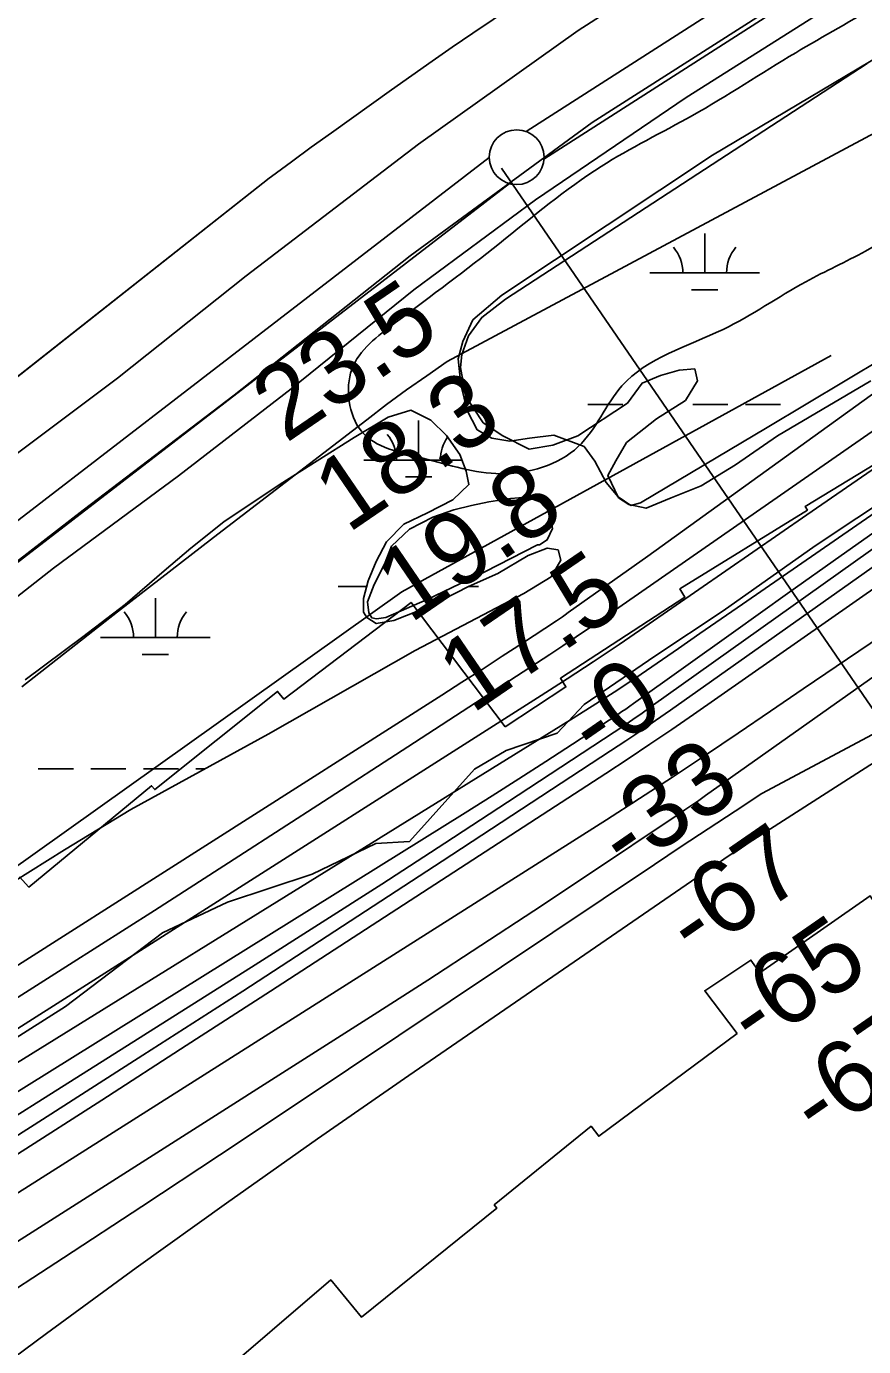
# Model space of a CAD drawing. Extents: x 3477039 to 3515015, y 546746 to 572297.
# Drawn here: x 3486854 to 3487619, y 561977 to 563182 of the extents above; entities that cross this region are included whole.
import ezdxf

# ---------------------------------------------------------------- set-up
doc = ezdxf.new("R2010")
doc.units = 0
for name, color, linetype in [('V-FLOD-BASE', 7, 'Continuous'), ('V-LEVE-TOET', 7, 'Continuous'), ('V-RIVR-EDGE', 7, 'Continuous'), ('V-RIVR-RANG', 7, 'Continuous'), ('V-ROAD-CNTR', 7, 'Continuous'), ('V-RRAP-FSHR', 7, 'Continuous'), ('V-RRAP-RVMT', 7, 'Continuous'), ('V-SITE-VEGE', 7, 'Continuous'), ('V-SURV-LINE', 7, 'Continuous'), ('V-TOPO-DPTH', 7, 'Continuous'), ('V-TOPO-MAJR', 7, 'Continuous'), ('V-TOPO-MINR', 7, 'Continuous'), ('V-TOPO-SHOR', 7, 'Continuous'), ('V-TOPO-WATR', 7, 'Continuous'), ('V-WETL-SWMP', 7, 'Continuous')]:
    doc.layers.add(name, color=color, linetype=linetype)

msp = doc.modelspace()

# ---------------------------------------------------------------- linework, layer by layer
at = {"layer": 'V-FLOD-BASE'}
msp.add_lwpolyline([(3487715.9, 563312.1), (3487656.2, 563272.9), (3487528.1, 563194.8), (3487371, 563094.6), (3487204.9, 562973), (3487043.9, 562845.9), (3486906.1, 562740.9), (3486744.7, 562616.2), (3486537, 562452.9), (3486382, 562333.4), (3486226.5, 562216.3), (3486049, 562077.7), (3485892.2, 561953), (3485879.2, 561940.8), (3485866.1, 561927.5), (3485851.7, 561900.1), (3485845.8, 561892.6), (3485832.2, 561886.9), (3485795.1, 561869.2), (3485769.7, 561854.8), (3485750.8, 561844.5), (3485730.7, 561826), (3485699.8, 561792.3), (3485690.8, 561775.5)], dxfattribs=at)
at = {"layer": 'V-LEVE-TOET'}
for points in [[(3486750.8, 562587.5), (3486879.1, 562687.9), (3486993.2, 562772.1), (3487096.2, 562851.8), (3487208, 562941.9), (3487319.2, 563024.3), (3487456.9, 563117.7), (3487586.8, 563199.3), (3487677.7, 563256.3), (3487671.7, 563230.2), (3487667.8, 563213), (3487719.3, 563259.3), (3487820.6, 563343.1), (3487922.4, 563411.9), (3488056.5, 563501.2), (3488248.5, 563623.2), (3488291.1, 563650.3), (3488313.4, 563664.6), (3488431, 563741.7), (3488574.5, 563830.8)], [(3484546.9, 561015), (3484692.5, 561128.1), (3484849.8, 561248.7), (3485030.2, 561384.9), (3485192.2, 561507.2), (3485354.9, 561634.2), (3485507.5, 561747.9), (3485642.4, 561857.6), (3485758.5, 561955.9), (3485787.5, 561980.7), (3485856.7, 562032.6), (3485991.5, 562132.4), (3486127.5, 562234.5), (3486285.4, 562351.1), (3486414.3, 562446.8), (3486552.1, 562554.2), (3486666.4, 562654.2), (3486800.7, 562759.3), (3486937.3, 562861.4), (3487055, 562954.9), (3487212.4, 563075), (3487358.4, 563178.7), (3487480.4, 563257.3), (3487605, 563337.8)]]:
    msp.add_lwpolyline(points, dxfattribs=at)
at = {"layer": 'V-RIVR-EDGE'}
msp.add_lwpolyline([(3488508.4, 563323), (3488448.2, 563295), (3488345.8, 563235.2), (3488231, 563170.5), (3488094.8, 563082), (3488051.8, 563050.8), (3487960.3, 562961), (3487863.3, 562893.2), (3487765.1, 562834.6), (3487574.9, 562708.3), (3487490.8, 562649.1), (3487428.2, 562607.5), (3487363.8, 562563.6), (3487339.2, 562537.3), (3487292.6, 562521.5), (3487263.7, 562504.4), (3487204.1, 562438.4), (3487173.5, 562436.6), (3487115.2, 562408.6), (3487037.9, 562383), (3486978.4, 562355), (3486890, 562287.8), (3486784.5, 562221.3)], dxfattribs=at)
at = {"layer": 'V-RIVR-RANG'}
msp.add_line((3487288.1, 563053), (3487831.8, 562261.8), dxfattribs=at)
at = {"layer": 'V-ROAD-CNTR'}
for points in [[(3487374.3, 563251.4), (3487355.5, 563239), (3487336.7, 563226.6), (3487317.9, 563214.1), (3487299.2, 563201.5), (3487280.5, 563188.9), (3487261.9, 563176.2), (3487243.3, 563163.4), (3487224.8, 563150.6), (3487206.3, 563137.7), (3487187.8, 563124.7), (3487169.4, 563111.6), (3487151.1, 563098.5), (3487132.8, 563085.4), (3487114.5, 563072.1), (3487096.3, 563058.8), (3487078.1, 563045.5), (3487076.1, 563044)], [(3487374.3, 563251.4), (3487355.5, 563239), (3487336.7, 563226.6), (3487317.9, 563214.1), (3487299.2, 563201.5), (3487280.5, 563188.9), (3487261.9, 563176.2), (3487243.3, 563163.4), (3487224.8, 563150.6), (3487206.3, 563137.7), (3487187.8, 563124.7), (3487169.4, 563111.6), (3487151.1, 563098.5), (3487132.8, 563085.4), (3487114.5, 563072.1), (3487096.3, 563058.8), (3487078.1, 563045.5), (3487076.1, 563044)], [(3487076.1, 563044), (3486779.2, 562810.3), (3486559.3, 562642), (3486392.2, 562506.5), (3486233.3, 562382.9), (3486038.4, 562229.6), (3485911.7, 562136), (3485621, 561911.1), (3485424, 561754.5), (3485308.3, 561665.3), (3485038, 561461.4), (3484792.2, 561271.1), (3484535.2, 561068.6), (3484336.9, 560919.3), (3484215.5, 560832), (3484122, 560761.2), (3483893.9, 560584.8), (3483720.5, 560448), (3483575.7, 560335.3), (3483437.8, 560223.9), (3483274.8, 560095.3), (3483188.4, 560027.1), (3483006, 559900.9)], [(3487076.1, 563044), (3486798.3, 562825.3)]]:
    msp.add_lwpolyline(points, dxfattribs=at)
msp.add_spline([(3488399.5, 563914), (3488406.3, 563902.4), (3488410.6, 563887.7), (3488411.4, 563873.4), (3488406.8, 563854.7), (3488385, 563828.9), (3488361.3, 563800.3), (3488342.5, 563772.7), (3488328.6, 563738.7), (3488294.5, 563679), (3488261.5, 563628.6), (3488225.6, 563589.8), (3488196.4, 563566.1), (3488126.9, 563526.6), (3488035.3, 563465.7), (3487944.9, 563406.5), (3487883.6, 563328.8), (3487846.5, 563300.4), (3487811.1, 563289.6), (3487768.8, 563287.8), (3487732, 563270.4), (3487634.3, 563203.9), (3487557, 563158.4), (3487462.6, 563101.1), (3487379.2, 563054.6), (3487286.4, 562984.4), (3487191.4, 562912.1), (3487151.5, 562869.4), (3487149.1, 562840.3), (3487160.2, 562813), (3487216.4, 562788.3), (3487287.7, 562774.2), (3487358.3, 562798.9), (3487398.2, 562854.3), (3487490.6, 562905.9), (3487566.3, 562949.4), (3487620.7, 562977.3), (3487709.5, 563034.4), (3487788.3, 563084.6), (3487906.6, 563182), (3488079.1, 563312.4), (3488206.2, 563398), (3488265.4, 563451.5), (3488263.6, 563511.9), (3488255.1, 563556.9), (3488256, 563586.9), (3488261.5, 563628.6)], degree=3, dxfattribs=at)
at = {"layer": 'V-RRAP-FSHR'}
msp.add_lwpolyline([(3484364.2, 560616.5), (3484735.6, 560876.4), (3485089.4, 561146.3), (3485314.8, 561319.6), (3485677.8, 561615.5), (3485963.4, 561819.7), (3486251.2, 561993), (3487197.2, 562666.3), (3487589.3, 562882.2)], dxfattribs=at)
at = {"layer": 'V-RRAP-RVMT'}
for points in [[(3488527.6, 563085.6), (3488415.5, 563015.6), (3488429.6, 562992.4), (3488301.6, 562913.8), (3488308.8, 562902.1), (3488195.8, 562832.9), (3488194, 562835.4), (3488083, 562763.8), (3488076.7, 562772.4), (3487943.2, 562689.3), (3487801.1, 562908.1), (3487684.6, 562835.7), (3487693, 562821.6), (3487565.7, 562744.3), (3487567.7, 562740.9), (3487451.2, 562669), (3487455.7, 562661.4), (3487342, 562587.5), (3487347.1, 562579.5), (3487291.5, 562543.2)], [(3487503.4, 562263.1), (3487473.9, 562302.2), (3487516.1, 562330.3), (3487524.3, 562318.7), (3487625, 562388.9), (3487628.2, 562384), (3487742, 562457.5), (3487764.4, 562422.2), (3487883.1, 562495.2), (3487902, 562466.9), (3488017.4, 562542.6), (3488027, 562528), (3488150, 562609), (3488155.5, 562600.1), (3488286.1, 562683.3), (3488267.8, 562714.5), (3488380.5, 562784.9), (3488391.6, 562769.2), (3488630.9, 562926.7)], [(3487291.5, 562543.2), (3487205.7, 562656.7), (3487089.3, 562568.4), (3487083.6, 562575.5), (3486971.5, 562485.8), (3486968.5, 562489.3), (3486856.3, 562396.8), (3486847.9, 562406.2)], [(3486787.8, 561781.4), (3486900.8, 561873.9), (3486911.2, 561862), (3487019.3, 561949), (3487023.1, 561944.8), (3487132.3, 562038.3), (3487160.4, 562004.2), (3487284, 562103.8), (3487281.6, 562106.7), (3487370.1, 562178.6), (3487377.1, 562169.4), (3487503.4, 562263.1)]]:
    msp.add_lwpolyline(points, dxfattribs=at)
at = {"layer": 'V-SITE-VEGE'}
msp.add_lwpolyline([(3487637.7, 562880.2), (3487530.9, 562816.5), (3487415.2, 562747.5), (3487406.4, 562745.3), (3487394.8, 562753), (3487383.8, 562766.1), (3487373.5, 562785.5), (3487363.7, 562799.1), (3487336.2, 562809.4), (3487313.9, 562806.7), (3487295.7, 562804), (3487279.4, 562806.6), (3487266, 562814.3), (3487256.8, 562832), (3487251.2, 562855.6), (3487248.6, 562879), (3487252.9, 562894.8), (3487261.9, 562914.6), (3487288.5, 562937.2), (3487481.1, 563065), (3487669.4, 563177)], dxfattribs=at)
at = {"layer": 'V-SURV-LINE'}
for points in [[(3487310.8, 563086.5), (3488549.3, 563878.8)], [(3488565.4, 563853.5), (3487327, 563061.2)], [(3483525, 560175.6), (3487277.1, 563062.8)], [(3487295.4, 563039), (3483543.3, 560151.8)]]:
    msp.add_lwpolyline(points, dxfattribs=at)
msp.add_circle((3487302.1, 563063.1), 25, dxfattribs=at)
at = {"layer": 'V-TOPO-DPTH'}
for points in [[(3489047.8, 563559.8), (3488100.8, 563061.7), (3488089.5, 563054.9), (3488078.2, 563047.9), (3488067.2, 563040.7), (3488056.2, 563033.4), (3487508.5, 562655.1), (3487489, 562641.6), (3487469.5, 562628.2), (3487450, 562614.7), (3487430.5, 562601.3), (3487410.9, 562588), (3487391.2, 562574.9), (3487371.2, 562562), (3487351.2, 562549.4), (3486662.9, 562123.5)], [(3486662.9, 562123.5), (3487351.2, 562549.4), (3487371.2, 562562), (3487391.2, 562574.9), (3487410.9, 562588), (3487430.5, 562601.3), (3487450, 562614.7), (3487469.5, 562628.2), (3487489, 562641.6), (3487508.5, 562655.1), (3488056.2, 563033.4), (3488067.2, 563040.7), (3488078.2, 563047.9), (3488089.5, 563054.9), (3488100.8, 563061.7), (3489047.8, 563559.8)], [(3488580.7, 563400.7), (3488473.6, 563340.5), (3488366.5, 563280.1), (3488259.5, 563219.6), (3488089, 563123), (3488067.4, 563110.5), (3488045.9, 563097.9), (3488024.7, 563084.9), (3488003.5, 563071.8), (3487982.5, 563058.3), (3487961.6, 563044.7), (3487941, 563030.8), (3487380.5, 562641.6), (3487368.5, 562633.4), (3487356.5, 562625.2), (3487344.4, 562617.2), (3487332.3, 562609.2), (3487202.7, 562524.9), (3487125.6, 562475), (3487048.4, 562425.2), (3486971.1, 562375.6), (3486893.7, 562326.2), (3486590, 562133.3)], [(3486846, 562153), (3486923.1, 562202.5), (3487000.1, 562252.2), (3487077.1, 562302), (3487383.7, 562500.6), (3487403.9, 562513.8), (3487423.9, 562527.2), (3487443.8, 562540.7), (3487463.7, 562554.4), (3487757.8, 562759.8), (3487816.2, 562800), (3487874.9, 562839.7), (3487934.2, 562878.7), (3487993.8, 562917.2), (3488062.2, 562960.6), (3488088, 562976.7), (3488114.1, 562992.3), (3488140.6, 563007.2), (3488167.4, 563021.8), (3488533.2, 563215)], [(3486846, 562153), (3486923.1, 562202.5), (3487000.1, 562252.2), (3487077.1, 562302), (3487383.7, 562500.6), (3487403.9, 562513.8), (3487423.9, 562527.2), (3487443.8, 562540.7), (3487463.7, 562554.4), (3487757.8, 562759.8), (3487816.2, 562800), (3487874.9, 562839.7), (3487934.2, 562878.7), (3487993.8, 562917.2), (3488062.2, 562960.6), (3488088, 562976.7), (3488114.1, 562992.3), (3488140.6, 563007.2), (3488167.4, 563021.8), (3488533.2, 563215)], [(3488512.8, 563176.7), (3488417.6, 563123.7), (3488322.7, 563070.3), (3488154.6, 562975), (3488144, 562968.8), (3488133.5, 562962.4), (3488123.1, 562955.8), (3488112.8, 562949.1), (3487563.8, 562577.7), (3487534, 562557.5), (3487504.3, 562537.3), (3487474.5, 562517.2), (3487444.5, 562497.3), (3487414.3, 562477.7), (3487384.1, 562458.3), (3486673.7, 562008.5)], [(3486673.7, 562008.5), (3487384.1, 562458.3), (3487414.3, 562477.7), (3487444.5, 562497.3), (3487474.5, 562517.2), (3487504.3, 562537.3), (3487534, 562557.5), (3487563.8, 562577.7), (3488112.8, 562949.1), (3488123.1, 562955.8), (3488133.5, 562962.4), (3488144, 562968.8), (3488154.6, 562975), (3488322.7, 563070.3), (3488417.6, 563123.7), (3488512.8, 563176.7)], [(3487796.3, 562825.6), (3487425.1, 562561.6), (3487416.8, 562555.7), (3487408.3, 562549.8), (3487399.9, 562544.1), (3487391.3, 562538.4), (3487293.8, 562474.4), (3487236.4, 562436.9), (3487178.8, 562399.6), (3487121, 562362.7), (3487063.1, 562325.9), (3486650.2, 562065.5)], [(3486650.2, 562065.5), (3487063.1, 562325.9), (3487121, 562362.7), (3487178.8, 562399.6), (3487236.4, 562436.9), (3487293.8, 562474.4), (3487391.3, 562538.4), (3487399.9, 562544.1), (3487408.3, 562549.8), (3487416.8, 562555.7), (3487425.1, 562561.6), (3487796.3, 562825.6)], [(3487717.1, 562651.8), (3487474.6, 562480.4), (3487468.4, 562476), (3487462.1, 562471.7), (3487455.8, 562467.4), (3487449.5, 562463.1), (3487366, 562407.2), (3487317.7, 562375.2), (3487269.4, 562343.4), (3487220.8, 562311.9), (3487172, 562280.7), (3486707.5, 561985.5)], [(3486707.5, 561985.5), (3487172, 562280.7), (3487220.8, 562311.9), (3487269.4, 562343.4), (3487317.7, 562375.2), (3487366, 562407.2), (3487449.5, 562463.1), (3487455.8, 562467.4), (3487462.1, 562471.7), (3487468.4, 562476), (3487474.6, 562480.4), (3487717.1, 562651.8)]]:
    msp.add_lwpolyline(points, dxfattribs=at)
at = {"layer": 'V-TOPO-MAJR'}
msp.add_lwpolyline([(3489124.2, 563429.5), (3488386.7, 562962.7), (3488356.8, 562943.6), (3488326.9, 562924.5), (3488297.2, 562905.2), (3488267.5, 562885.7), (3488219.7, 562854.2), (3488214, 562850.5), (3488208.2, 562846.8), (3488202.4, 562843.1), (3488196.6, 562839.5), (3487526.2, 562482.2), (3487501.6, 562466.2), (3487477, 562450), (3487452.4, 562433.8), (3487427.9, 562417.5), (3487101.6, 562199.3), (3487030.7, 562152.1), (3486959.6, 562105.2), (3486888.2, 562058.6), (3486816.7, 562012.2)], dxfattribs=at)
at = {"layer": 'V-TOPO-MINR'}
for points in [[(3488401.9, 563529.5), (3488382.5, 563515.7), (3487967, 563269.3), (3487955.5, 563262.5), (3487943.9, 563255.8), (3487932.3, 563249.2), (3487920.7, 563242.6), (3487839.9, 563197.5), (3487831.4, 563193.4), (3487238.7, 562876.5), (3487220.1, 562863.6), (3487201.6, 562850.6), (3487183.3, 562837.2), (3487165.2, 562823.5), (3487025, 562716.1), (3486937.3, 562648.1), (3486850, 562579.6)], [(3488714.5, 563436.6), (3488109.1, 563094.4), (3488086.9, 563081.6), (3488064.9, 563068.5), (3488043.2, 563054.9), (3488021.7, 563041.1), (3487897.9, 562959.6), (3487814.7, 562904.5), (3487731.9, 562849.1), (3487649.4, 562793.1), (3487567.2, 562736.7), (3487419.2, 562634.4), (3487395.7, 562618.4), (3487372.1, 562602.5), (3487348.3, 562587), (3487324.4, 562571.6), (3486975.2, 562349.7), (3486905.8, 562305.6), (3486836.3, 562261.5)], [(3488508.1, 563411.4), (3488386.6, 563342.2), (3488265.4, 563272.7), (3488046.8, 563146.5), (3488035.2, 563139.5), (3488023.7, 563132.4), (3487421.9, 562699), (3487349.2, 562647.4), (3487346.5, 562645.5), (3487343.9, 562643.6), (3487341.2, 562641.8), (3487338.4, 562640), (3487307.3, 562619.5), (3487288.9, 562607.5), (3487270.6, 562595.6), (3487252.1, 562583.8), (3487233.7, 562572), (3486596.8, 562166.8)], [(3488580.7, 563400.7), (3488473.6, 563340.5), (3488366.5, 563280.1), (3488259.5, 563219.6), (3488089, 563123), (3488067.4, 563110.5), (3488045.9, 563097.9), (3488024.7, 563084.9), (3488003.5, 563071.8), (3487982.5, 563058.3), (3487961.6, 563044.7), (3487941, 563030.8), (3487380.5, 562641.6), (3487368.5, 562633.4), (3487356.5, 562625.2), (3487344.4, 562617.2), (3487332.3, 562609.2), (3487202.7, 562524.9), (3487125.6, 562475), (3487048.4, 562425.2), (3486971.1, 562375.6), (3486893.7, 562326.2), (3486590, 562133.3)], [(3488743.8, 563378.4), (3488097.5, 563047.9), (3488090.6, 563043.8), (3488083.7, 563039.5), (3488076.9, 563035), (3488070.2, 563030.5), (3487697.5, 562769.2), (3487648.1, 562734.5), (3487598.7, 562699.6), (3487549.4, 562664.7), (3487500.2, 562629.6), (3487408.9, 562564.4), (3487405.4, 562561.9), (3487401.8, 562559.4), (3487398.1, 562557), (3487394.5, 562554.5), (3487353.1, 562527.4), (3487328.7, 562511.5), (3487304.2, 562495.7), (3487279.6, 562480.1), (3487254.9, 562464.6), (3486655.9, 562091.8)], [(3488694.5, 563316.1), (3488116.9, 563024.6), (3488099.4, 563015.1), (3488082.1, 563005.2), (3488065, 562995), (3488048.1, 562984.4), (3488031.4, 562973.6), (3488014.9, 562962.5), (3487998.5, 562951.2), (3487442.6, 562558.4), (3487429, 562548.9), (3487415.4, 562539.6), (3487401.7, 562530.4), (3487387.9, 562521.2), (3487233.9, 562420.4), (3487142.9, 562361.1), (3487051.8, 562302), (3486960.5, 562243.3), (3486869, 562184.7), (3486645.3, 562042.2)], [(3488533.2, 563215), (3488167.4, 563021.8), (3488140.6, 563007.2), (3488114.1, 562992.3), (3488088, 562976.7), (3488062.2, 562960.6), (3487993.8, 562917.2), (3487934.2, 562878.7), (3487874.9, 562839.7), (3487816.2, 562800), (3487757.8, 562759.8), (3487463.7, 562554.4), (3487443.8, 562540.7), (3487423.9, 562527.2), (3487403.9, 562513.8), (3487383.7, 562500.6), (3487077.1, 562302), (3487000.1, 562252.2), (3486923.1, 562202.5), (3486846, 562153)], [(3488512.8, 563176.7), (3488417.6, 563123.7), (3488322.7, 563070.3), (3488154.6, 562975), (3488144, 562968.8), (3488133.5, 562962.4), (3488123.1, 562955.8), (3488112.8, 562949.1), (3487563.8, 562577.7), (3487534, 562557.5), (3487504.3, 562537.3), (3487474.5, 562517.2), (3487444.5, 562497.3), (3487414.3, 562477.7), (3487384.1, 562458.3), (3486673.7, 562008.5)], [(3488501.3, 562984.2), (3488286.8, 562840.4), (3488260.7, 562823.2), (3488234.5, 562806.1), (3488208.1, 562789.3), (3488181.6, 562772.8), (3487691, 562542.4), (3487668.3, 562532.3), (3487646.3, 562520.7), (3487624.8, 562508), (3487517.9, 562439.7), (3487506.2, 562432.1), (3487494.5, 562424.5), (3487483, 562416.7), (3487471.5, 562408.9), (3487203.6, 562224.9), (3487120.1, 562167), (3487037.1, 562108.5), (3486954.6, 562049.2), (3486872.6, 561989.3), (3486762.2, 561907.9)], [(3487796.3, 562825.6), (3487425.1, 562561.6), (3487416.8, 562555.7), (3487408.3, 562549.8), (3487399.9, 562544.1), (3487391.3, 562538.4), (3487293.8, 562474.4), (3487236.4, 562436.9), (3487178.8, 562399.6), (3487121, 562362.7), (3487063.1, 562325.9), (3486650.2, 562065.5)], [(3487717.1, 562651.8), (3487474.6, 562480.4), (3487468.4, 562476), (3487462.1, 562471.7), (3487455.8, 562467.4), (3487449.5, 562463.1), (3487366, 562407.2), (3487317.7, 562375.2), (3487269.4, 562343.4), (3487220.8, 562311.9), (3487172, 562280.7), (3486707.5, 561985.5)]]:
    msp.add_lwpolyline(points, dxfattribs=at)
at = {"layer": 'V-TOPO-SHOR'}
msp.add_lwpolyline([(3487321.2, 562709.3), (3487272.9, 562684.6), (3487220.4, 562659.5), (3487182.7, 562642.9), (3487173.9, 562641.8), (3487169.8, 562642.5), (3487166.9, 562647.2), (3487165.9, 562657.2), (3487171.9, 562672.9), (3487181.5, 562691.6), (3487187.6, 562707.9), (3487204.2, 562723.5), (3487225.4, 562734.4), (3487244.8, 562741.2), (3487260.7, 562745.1), (3487276.6, 562748.5), (3487296.5, 562751.7), (3487311.8, 562752.7), (3487323.4, 562748.5), (3487332.1, 562739), (3487334.9, 562724.3), (3487330.1, 562713.8), (3487323, 562709.2), (3487321.2, 562709.3)], dxfattribs=at)
at = {"layer": 'V-TOPO-WATR'}
msp.add_lwpolyline([(3489047.8, 563559.8), (3488100.8, 563061.7), (3488089.5, 563054.9), (3488078.2, 563047.9), (3488067.2, 563040.7), (3488056.2, 563033.4), (3487508.5, 562655.1), (3487489, 562641.6), (3487469.5, 562628.2), (3487450, 562614.7), (3487430.5, 562601.3), (3487410.9, 562588), (3487391.2, 562574.9), (3487371.2, 562562), (3487351.2, 562549.4), (3486662.9, 562123.5)], dxfattribs=at)
at = {"layer": 'V-WETL-SWMP'}
for p, q in [((3487473.9, 562957.4), (3487473.9, 562993.4)), ((3487423.9, 562957.4), (3487523.9, 562957.4)), ((3487461.9, 562942), (3487485.9, 562942)), ((3487367.1, 562837.3), (3487399.1, 562837.3)), ((3487463.1, 562837.3), (3487495.1, 562837.3)), ((3487511.1, 562837.3), (3487543.1, 562837.3)), ((3487212.5, 562786.6), (3487212.5, 562822.6)), ((3487162.5, 562786.6), (3487252.1, 562786.6)), ((3487200.5, 562771.2), (3487224.5, 562771.2)), ((3487139.1, 562671.2), (3487165.1, 562671.2)), ((3487258.2, 562671.2), (3487267.1, 562671.2)), ((3486972, 562624.7), (3486972, 562660.7)), ((3486922, 562624.7), (3487022, 562624.7)), ((3486960, 562609.3), (3486984, 562609.3)), ((3486865.1, 562504.7), (3486897.1, 562504.7)), ((3486913.1, 562504.7), (3486945.1, 562504.7)), ((3486961.1, 562504.7), (3486993.1, 562504.7)), ((3487009.1, 562504.7), (3487017.3, 562504.7))]:
    msp.add_line(p, q, dxfattribs=at)
for points in [[(3487625.8, 562859.1), (3487581.3, 562832.7), (3487540.5, 562808.6), (3487502, 562782.2), (3487470.8, 562763), (3487443.2, 562752.2), (3487420.3, 562742.6), (3487404.7, 562746.2), (3487395.1, 562752.2), (3487385.5, 562772.6), (3487392.7, 562785.8), (3487402.3, 562802.6), (3487429.9, 562824.3), (3487456.4, 562841.1), (3487467.2, 562859.1), (3487464.8, 562869.9), (3487450.4, 562868.7), (3487433.6, 562863.9), (3487416.7, 562856.7), (3487403.5, 562838.7), (3487357.9, 562808.6), (3487335, 562800.2), (3487313.4, 562796.6), (3487289.4, 562808.6), (3487271.4, 562820.7), (3487255.8, 562844.7), (3487250.9, 562871.1), (3487252.1, 562883.1), (3487258.2, 562899.9), (3487270.2, 562916.8), (3487291.8, 562933.6), (3487622.2, 563148.6)], [(3486853, 562586), (3486905.8, 562625.3), (3486944.5, 562654.9), (3486980, 562685.4), (3487004.5, 562706.2), (3487034.5, 562730.1), (3487086.1, 562764.7), (3487153.5, 562807.3), (3487184.6, 562825.7), (3487205.4, 562832.1), (3487223.6, 562823.2), (3487237.9, 562809), (3487250.2, 562791.7), (3487255.9, 562776.4), (3487258.5, 562764.2), (3487243.9, 562750.3), (3487220.7, 562738.5), (3487199.1, 562728.2), (3487183.2, 562711.9), (3487173.6, 562694.1), (3487166.4, 562676.5), (3487162.3, 562660.2), (3487162.1, 562647.7), (3487165.2, 562642.9), (3487173.8, 562637.4), (3487189.8, 562640.3), (3487223.2, 562653.2), (3487258.2, 562671.2), (3487284.9, 562683), (3487312.5, 562699.5), (3487330.1, 562706.3), (3487339.9, 562704.6), (3487342.5, 562695.2), (3487333.7, 562680.1), (3487308.6, 562664.7), (3487209.4, 562612.7), (3487075.2, 562536.5), (3486949.7, 562467.6), (3486889.1, 562430.8), (3486826.5, 562392)]]:
    msp.add_lwpolyline(points, dxfattribs=at)
for centre, start, end in [((3487418.7, 562957.9), 359.2282, 40.7718), ((3487529.1, 562957.9), 139.2282, 180.7718), ((3487157.2, 562787.1), 359.2282, 40.7718), ((3487267.7, 562787.1), 144.5769, 180.7718), ((3486916.8, 562625.2), 359.2282, 40.7718), ((3487027.2, 562625.2), 139.2282, 180.7718)]:
    msp.add_arc(centre, 35.2, start, end, dxfattribs=at)

# ---------------------------------------------------------------- texts
at = {"layer": 'V-RIVR-RANG'}
for s, rotation, p in [('23.5', 34.3683, (3487091.2, 562801.5)), ('18.3', 34.3683, (3487147.8, 562719.1)), ('19.8', 34.3683, (3487204.5, 562636.7)), ('17.5', 34.3683, (3487261.1, 562554.3)), ('-0', 34.6549, (3487374.7, 562510.5)), ('-33', 34.6549, (3487402.5, 562408.1)), ('-67', 34.6549, (3487464.6, 562329.5)), ('-65', 34.6549, (3487520.1, 562246.3)), ('-67', 34.6549, (3487577.9, 562164.7))]:
    msp.add_text(s, height=67, rotation=rotation, dxfattribs=at).set_placement(p)

doc.saveas('drawing.dxf')
